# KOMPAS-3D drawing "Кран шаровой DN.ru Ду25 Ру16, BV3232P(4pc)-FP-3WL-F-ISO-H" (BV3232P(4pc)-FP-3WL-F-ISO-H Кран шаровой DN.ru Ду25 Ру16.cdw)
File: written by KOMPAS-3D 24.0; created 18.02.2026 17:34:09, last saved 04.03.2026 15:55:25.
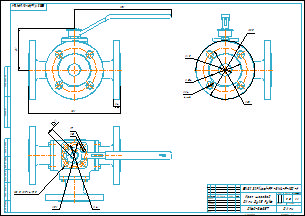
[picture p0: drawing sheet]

Document properties: Автор: R2D2; Форматы листов документа: A2; Полное имя файла: BV3232P(4pc)-FP-3WL-F-ISO-H Кран шаровой DN.ru Ду25 Ру16.m3d; Масса: 5.6; Наименование: Кран шаровой DN.ru Ду25 Ру16; Количество листов документа: 1; Примечание: D160-36357

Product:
- Part/product: Кран шаровой DN.ru Ду25 Ру16  | designation BV3232P(4pc)-FP-3WL-F-ISO-H
    Масса: 5.6
    Раздел спецификации: Прочие изделия
    Примечание: D160-36357

Views: Вид 1, Спереди, Проекционный вид 2
Referenced files in E:\Работа\Зайцев\BV3232P(4pc)-FP-3WL-F-ISO-H Кран шаровой DN.ru Ду15-100 Ру16\DN25\: BV3232P(4pc)-FP-3WL-F-ISO-H Кран шаровой DN.ru Ду25 Ру16.m3d
Referenced files in E:\Работа\Зайцев\Для компаса\: чертеж DN.ru А3.cdt
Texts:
  BV3232P(4pc)-FP-3WL-F-ISO-H
  чертеж DN.ru А3.cdt
  Кран шаровой
  DN.ru Ду25 Ру16
  Кран шаровой DN.ru Ду25 Ру16
  BV3232P(4pc)-FP-3WL-F-ISO-H Кран шаровой DN.ru Ду25 Ру16
Dimensions and other numbers on the sheet: 0; 3; 2; 4; 180; 14; 82; 190; 115; 85; 64; 25; 4 отв.; 1:1; 1; 5,6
